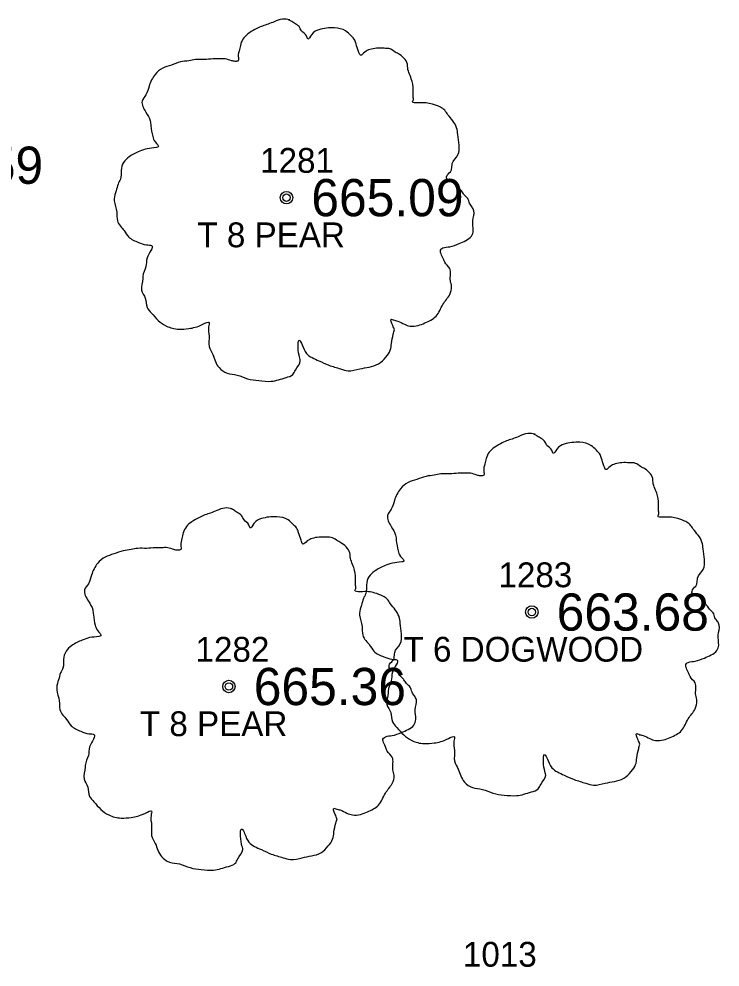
# Model space of a CAD drawing. Extents: x 1655137 to 1657928, y 1003994 to 1005407.
# Drawn here: x 1656195.93 to 1656224.19, y 1004707.02 to 1004745.24 of the extents above; entities that cross this region are included whole.
import ezdxf

# ---------------------------------------------------------------- set-up
doc = ezdxf.new("R2010")
doc.units = 0
for name, color, linetype in [('RD_EX_DV_Prop_txCode', 7, 'Continuous'), ('RD_EX_TX_Driveway_ELEV', 7, 'Continuous'), ('RD_EX_TX_VEG_ELEV', 7, 'Continuous'), ('RD_EX_VEG', 7, 'Continuous'), ('RD_EX_VEG_txCode', 7, 'Continuous'), ('RD_SMD_Locator', 7, 'Continuous')]:
    doc.layers.add(name, color=color, linetype=linetype)

msp = doc.modelspace()

# ---------------------------------------------------------------- linework, layer by layer
at = {"layer": 'RD_EX_VEG'}
for centre, radius in [((1656206.716, 1004738.034), 0.25), ((1656206.703, 1004738.015), 0.0001), ((1656216.604, 1004721.331), 0.25), ((1656216.592, 1004721.312), 0.0001), ((1656204.396, 1004718.329), 0.25), ((1656204.384, 1004718.311), 0.0001)]:
    msp.add_circle(centre, radius, dxfattribs=at)
for points in [[(1656206.848, 1004745.201), (1656206.548, 1004745.226), (1656206.223, 1004745.126), (1656205.973, 1004745.026), (1656205.748, 1004744.951), (1656205.523, 1004744.851), (1656205.223, 1004744.677), (1656204.998, 1004744.477), (1656204.873, 1004744.227), (1656204.823, 1004744.002), (1656204.773, 1004743.727), (1656204.773, 1004743.552), (1656204.649, 1004743.527), (1656204.499, 1004743.552), (1656204.249, 1004743.627), (1656203.999, 1004743.627), (1656203.749, 1004743.627), (1656203.399, 1004743.602), (1656203.049, 1004743.602), (1656202.774, 1004743.552), (1656202.449, 1004743.502), (1656202.075, 1004743.377), (1656201.725, 1004743.252), (1656201.425, 1004743.002), (1656201.175, 1004742.528), (1656201.05, 1004742.178), (1656200.9, 1004741.928), (1656201.05, 1004741.478), (1656201.225, 1004741.128), (1656201.25, 1004740.928), (1656201.325, 1004740.503), (1656201.425, 1004740.279), (1656201.55, 1004740.079), (1656201.475, 1004740.054), (1656201.1, 1004740.004), (1656200.8, 1004739.904), (1656200.375, 1004739.679), (1656200.15, 1004739.454), (1656200.05, 1004739.129), (1656200.026, 1004738.779), (1656199.926, 1004738.579), (1656199.851, 1004738.304), (1656199.826, 1004738.229), (1656199.776, 1004737.905), (1656199.876, 1004737.455), (1656199.901, 1004737.105), (1656200.026, 1004736.88), (1656200.175, 1004736.705), (1656200.35, 1004736.455), (1656200.75, 1004736.23), (1656201.075, 1004736.13), (1656201.275, 1004736.105), (1656201.1, 1004735.606), (1656201.05, 1004735.256), (1656200.925, 1004734.856), (1656200.925, 1004734.781), (1656200.875, 1004734.306), (1656201.025, 1004733.981), (1656201.1, 1004733.606), (1656201.275, 1004733.382), (1656201.55, 1004733.082), (1656201.875, 1004732.857), (1656202.375, 1004732.732), (1656202.774, 1004732.757), (1656203.349, 1004732.932), (1656203.599, 1004733.007), (1656203.574, 1004732.832), (1656203.599, 1004732.457), (1656203.599, 1004732.032), (1656203.749, 1004731.707), (1656203.849, 1004731.432), (1656203.999, 1004731.182), (1656204.324, 1004730.958), (1656204.723, 1004730.883), (1656205.148, 1004730.733), (1656205.598, 1004730.658), (1656206.098, 1004730.633), (1656206.698, 1004730.783), (1656206.972, 1004730.908), (1656207.072, 1004731.083), (1656207.272, 1004731.457), (1656207.222, 1004731.682), (1656207.247, 1004732.282), (1656207.347, 1004732.107), (1656207.522, 1004731.757), (1656208.022, 1004731.457), (1656208.422, 1004731.282), (1656208.897, 1004731.132), (1656209.197, 1004731.058), (1656209.671, 1004731.132), (1656210.046, 1004731.207), (1656210.421, 1004731.332), (1656210.721, 1004731.607), (1656210.896, 1004731.882), (1656210.946, 1004732.157), (1656211.021, 1004732.532), (1656211.071, 1004732.707)], [(1656211.071, 1004732.707), (1656210.996, 1004732.882), (1656210.946, 1004733.132), (1656211.021, 1004733.107), (1656211.196, 1004733.057), (1656211.471, 1004732.932), (1656211.695, 1004732.857), (1656212.02, 1004732.882), (1656212.295, 1004732.982), (1656212.745, 1004733.257), (1656213.02, 1004733.731), (1656213.295, 1004734.131), (1656213.37, 1004734.456), (1656213.32, 1004734.681), (1656213.295, 1004735.181), (1656213.095, 1004735.431), (1656213.045, 1004735.556), (1656212.945, 1004735.955), (1656213.02, 1004736.005), (1656213.295, 1004736.055), (1656213.67, 1004736.18), (1656213.944, 1004736.305), (1656214.169, 1004736.48), (1656214.244, 1004736.705), (1656214.219, 1004737.105), (1656214.269, 1004737.505), (1656214.194, 1004737.655), (1656214.094, 1004737.805), (1656214.019, 1004738.005), (1656213.869, 1004738.154), (1656213.77, 1004738.304), (1656213.67, 1004738.404), (1656213.545, 1004738.554), (1656213.37, 1004738.679), (1656213.22, 1004738.729), (1656213.17, 1004738.879), (1656213.32, 1004739.079), (1656213.37, 1004739.179), (1656213.395, 1004739.404), (1656213.62, 1004739.754), (1656213.67, 1004740.154), (1656213.62, 1004740.578), (1656213.57, 1004740.853), (1656213.42, 1004741.128), (1656213.22, 1004741.378), (1656213.095, 1004741.553), (1656212.92, 1004741.678), (1656212.595, 1004741.803), (1656212.345, 1004741.853), (1656211.995, 1004741.853), (1656211.795, 1004741.903), (1656211.82, 1004741.953), (1656211.82, 1004742.103), (1656211.82, 1004742.378), (1656211.745, 1004742.827), (1656211.595, 1004743.327), (1656211.595, 1004743.352), (1656211.495, 1004743.602), (1656211.271, 1004743.802), (1656211.096, 1004743.902), (1656210.896, 1004744.027), (1656210.646, 1004744.052), (1656210.346, 1004744.052), (1656210.071, 1004744.002), (1656209.871, 1004743.902), (1656209.696, 1004743.777), (1656209.621, 1004743.927), (1656209.521, 1004744.227), (1656209.471, 1004744.377), (1656209.321, 1004744.552), (1656209.097, 1004744.752), (1656208.647, 1004744.876), (1656208.022, 1004744.802), (1656207.722, 1004744.602), (1656207.572, 1004744.427), (1656207.522, 1004744.552), (1656207.322, 1004744.752), (1656207.222, 1004744.926), (1656207.047, 1004745.051), (1656206.898, 1004745.151), (1656206.798, 1004745.201)], [(1656216.736, 1004728.498), (1656216.436, 1004728.523), (1656216.112, 1004728.423), (1656215.862, 1004728.324), (1656215.637, 1004728.249), (1656215.412, 1004728.149), (1656215.112, 1004727.974), (1656214.887, 1004727.774), (1656214.762, 1004727.524), (1656214.712, 1004727.299), (1656214.662, 1004727.024), (1656214.662, 1004726.849), (1656214.537, 1004726.824), (1656214.387, 1004726.849), (1656214.137, 1004726.924), (1656213.887, 1004726.924), (1656213.638, 1004726.924), (1656213.288, 1004726.899), (1656212.938, 1004726.899), (1656212.663, 1004726.849), (1656212.338, 1004726.799), (1656211.963, 1004726.674), (1656211.613, 1004726.549), (1656211.314, 1004726.299), (1656211.064, 1004725.825), (1656210.939, 1004725.475), (1656210.789, 1004725.225), (1656210.939, 1004724.775), (1656211.114, 1004724.425), (1656211.139, 1004724.225), (1656211.214, 1004723.801), (1656211.314, 1004723.576), (1656211.439, 1004723.376), (1656211.364, 1004723.351), (1656210.989, 1004723.301), (1656210.689, 1004723.201), (1656210.264, 1004722.976), (1656210.039, 1004722.751), (1656209.939, 1004722.426), (1656209.914, 1004722.076), (1656209.814, 1004721.876), (1656209.739, 1004721.601), (1656209.714, 1004721.526), (1656209.664, 1004721.202), (1656209.764, 1004720.752), (1656209.789, 1004720.402), (1656209.914, 1004720.177), (1656210.064, 1004720.002), (1656210.239, 1004719.752), (1656210.639, 1004719.527), (1656210.964, 1004719.427), (1656211.164, 1004719.402), (1656210.989, 1004718.903), (1656210.939, 1004718.553), (1656210.814, 1004718.153), (1656210.814, 1004718.078), (1656210.764, 1004717.603), (1656210.914, 1004717.278), (1656210.989, 1004716.904), (1656211.164, 1004716.679), (1656211.439, 1004716.379), (1656211.763, 1004716.154), (1656212.263, 1004716.029), (1656212.663, 1004716.054), (1656213.238, 1004716.229), (1656213.488, 1004716.304), (1656213.463, 1004716.129), (1656213.488, 1004715.754), (1656213.488, 1004715.329), (1656213.638, 1004715.004), (1656213.738, 1004714.729), (1656213.887, 1004714.48), (1656214.212, 1004714.255), (1656214.612, 1004714.18), (1656215.037, 1004714.03), (1656215.487, 1004713.955), (1656215.987, 1004713.93), (1656216.586, 1004714.08), (1656216.861, 1004714.205), (1656216.961, 1004714.38), (1656217.161, 1004714.754), (1656217.111, 1004714.979), (1656217.136, 1004715.579), (1656217.236, 1004715.404), (1656217.411, 1004715.054), (1656217.911, 1004714.754), (1656218.311, 1004714.58), (1656218.785, 1004714.43), (1656219.085, 1004714.355), (1656219.56, 1004714.43), (1656219.935, 1004714.505), (1656220.31, 1004714.63), (1656220.61, 1004714.904), (1656220.784, 1004715.179), (1656220.834, 1004715.454), (1656220.909, 1004715.829), (1656220.959, 1004716.004)], [(1656220.959, 1004716.004), (1656220.884, 1004716.179), (1656220.834, 1004716.429), (1656220.909, 1004716.404), (1656221.084, 1004716.354), (1656221.359, 1004716.229), (1656221.584, 1004716.154), (1656221.909, 1004716.179), (1656222.184, 1004716.279), (1656222.634, 1004716.554), (1656222.909, 1004717.028), (1656223.183, 1004717.428), (1656223.258, 1004717.753), (1656223.208, 1004717.978), (1656223.183, 1004718.478), (1656222.983, 1004718.728), (1656222.933, 1004718.853), (1656222.834, 1004719.252), (1656222.909, 1004719.302), (1656223.183, 1004719.352), (1656223.558, 1004719.477), (1656223.833, 1004719.602), (1656224.058, 1004719.777), (1656224.133, 1004720.002), (1656224.108, 1004720.402), (1656224.158, 1004720.802), (1656224.083, 1004720.952), (1656223.983, 1004721.102), (1656223.908, 1004721.302), (1656223.758, 1004721.451), (1656223.658, 1004721.601), (1656223.558, 1004721.701), (1656223.433, 1004721.851), (1656223.258, 1004721.976), (1656223.108, 1004722.026), (1656223.058, 1004722.176), (1656223.208, 1004722.376), (1656223.258, 1004722.476), (1656223.283, 1004722.701), (1656223.508, 1004723.051), (1656223.558, 1004723.451), (1656223.508, 1004723.875), (1656223.458, 1004724.15), (1656223.308, 1004724.425), (1656223.108, 1004724.675), (1656222.983, 1004724.85), (1656222.809, 1004724.975), (1656222.484, 1004725.1), (1656222.234, 1004725.15), (1656221.884, 1004725.15), (1656221.684, 1004725.2), (1656221.709, 1004725.25), (1656221.709, 1004725.4), (1656221.709, 1004725.675), (1656221.634, 1004726.124), (1656221.484, 1004726.624), (1656221.484, 1004726.649), (1656221.384, 1004726.899), (1656221.159, 1004727.099), (1656220.984, 1004727.199), (1656220.784, 1004727.324), (1656220.535, 1004727.349), (1656220.235, 1004727.349), (1656219.96, 1004727.299), (1656219.76, 1004727.199), (1656219.585, 1004727.074), (1656219.51, 1004727.224), (1656219.41, 1004727.524), (1656219.36, 1004727.674), (1656219.21, 1004727.849), (1656218.985, 1004728.049), (1656218.535, 1004728.174), (1656217.911, 1004728.099), (1656217.611, 1004727.899), (1656217.461, 1004727.724), (1656217.411, 1004727.849), (1656217.211, 1004728.049), (1656217.111, 1004728.224), (1656216.936, 1004728.349), (1656216.786, 1004728.448), (1656216.686, 1004728.498)], [(1656204.528, 1004725.497), (1656204.228, 1004725.522), (1656203.903, 1004725.422), (1656203.654, 1004725.322), (1656203.429, 1004725.247), (1656203.204, 1004725.147), (1656202.904, 1004724.972), (1656202.679, 1004724.772), (1656202.554, 1004724.522), (1656202.504, 1004724.297), (1656202.454, 1004724.022), (1656202.454, 1004723.847), (1656202.329, 1004723.822), (1656202.179, 1004723.847), (1656201.929, 1004723.922), (1656201.679, 1004723.922), (1656201.429, 1004723.922), (1656201.08, 1004723.897), (1656200.73, 1004723.897), (1656200.455, 1004723.847), (1656200.13, 1004723.797), (1656199.755, 1004723.672), (1656199.405, 1004723.547), (1656199.106, 1004723.298), (1656198.856, 1004722.823), (1656198.731, 1004722.473), (1656198.581, 1004722.223), (1656198.731, 1004721.773), (1656198.906, 1004721.423), (1656198.931, 1004721.223), (1656199.006, 1004720.799), (1656199.106, 1004720.574), (1656199.23, 1004720.374), (1656199.156, 1004720.349), (1656198.781, 1004720.299), (1656198.481, 1004720.199), (1656198.056, 1004719.974), (1656197.831, 1004719.749), (1656197.731, 1004719.424), (1656197.706, 1004719.074), (1656197.606, 1004718.875), (1656197.531, 1004718.6), (1656197.506, 1004718.525), (1656197.456, 1004718.2), (1656197.556, 1004717.75), (1656197.581, 1004717.4), (1656197.706, 1004717.175), (1656197.856, 1004717), (1656198.031, 1004716.75), (1656198.431, 1004716.526), (1656198.756, 1004716.426), (1656198.956, 1004716.401), (1656198.781, 1004715.901), (1656198.731, 1004715.551), (1656198.606, 1004715.151), (1656198.606, 1004715.076), (1656198.556, 1004714.601), (1656198.706, 1004714.276), (1656198.781, 1004713.902), (1656198.956, 1004713.677), (1656199.23, 1004713.377), (1656199.555, 1004713.152), (1656200.055, 1004713.027), (1656200.455, 1004713.052), (1656201.03, 1004713.227), (1656201.28, 1004713.302), (1656201.255, 1004713.127), (1656201.28, 1004712.752), (1656201.28, 1004712.327), (1656201.429, 1004712.003), (1656201.529, 1004711.728), (1656201.679, 1004711.478), (1656202.004, 1004711.253), (1656202.404, 1004711.178), (1656202.829, 1004711.028), (1656203.279, 1004710.953), (1656203.778, 1004710.928), (1656204.378, 1004711.078), (1656204.653, 1004711.203), (1656204.753, 1004711.378), (1656204.953, 1004711.753), (1656204.903, 1004711.978), (1656204.928, 1004712.577), (1656205.028, 1004712.402), (1656205.203, 1004712.052), (1656205.703, 1004711.753), (1656206.102, 1004711.578), (1656206.577, 1004711.428), (1656206.877, 1004711.353), (1656207.352, 1004711.428), (1656207.727, 1004711.503), (1656208.102, 1004711.628), (1656208.401, 1004711.903), (1656208.576, 1004712.177), (1656208.626, 1004712.452), (1656208.701, 1004712.827), (1656208.751, 1004713.002)], [(1656208.751, 1004713.002), (1656208.676, 1004713.177), (1656208.626, 1004713.427), (1656208.701, 1004713.402), (1656208.876, 1004713.352), (1656209.151, 1004713.227), (1656209.376, 1004713.152), (1656209.701, 1004713.177), (1656209.976, 1004713.277), (1656210.426, 1004713.552), (1656210.7, 1004714.027), (1656210.975, 1004714.426), (1656211.05, 1004714.751), (1656211, 1004714.976), (1656210.975, 1004715.476), (1656210.775, 1004715.726), (1656210.725, 1004715.851), (1656210.625, 1004716.251), (1656210.7, 1004716.301), (1656210.975, 1004716.351), (1656211.35, 1004716.476), (1656211.625, 1004716.6), (1656211.85, 1004716.775), (1656211.925, 1004717), (1656211.9, 1004717.4), (1656211.95, 1004717.8), (1656211.875, 1004717.95), (1656211.775, 1004718.1), (1656211.7, 1004718.3), (1656211.55, 1004718.45), (1656211.45, 1004718.6), (1656211.35, 1004718.7), (1656211.225, 1004718.85), (1656211.05, 1004718.974), (1656210.9, 1004719.024), (1656210.85, 1004719.174), (1656211, 1004719.374), (1656211.05, 1004719.474), (1656211.075, 1004719.699), (1656211.3, 1004720.049), (1656211.35, 1004720.449), (1656211.3, 1004720.874), (1656211.25, 1004721.149), (1656211.1, 1004721.423), (1656210.9, 1004721.673), (1656210.775, 1004721.848), (1656210.6, 1004721.973), (1656210.276, 1004722.098), (1656210.026, 1004722.148), (1656209.676, 1004722.148), (1656209.476, 1004722.198), (1656209.501, 1004722.248), (1656209.501, 1004722.398), (1656209.501, 1004722.673), (1656209.426, 1004723.123), (1656209.276, 1004723.622), (1656209.276, 1004723.647), (1656209.176, 1004723.897), (1656208.951, 1004724.097), (1656208.776, 1004724.197), (1656208.576, 1004724.322), (1656208.326, 1004724.347), (1656208.027, 1004724.347), (1656207.752, 1004724.297), (1656207.552, 1004724.197), (1656207.377, 1004724.072), (1656207.302, 1004724.222), (1656207.202, 1004724.522), (1656207.152, 1004724.672), (1656207.002, 1004724.847), (1656206.777, 1004725.047), (1656206.327, 1004725.172), (1656205.703, 1004725.097), (1656205.403, 1004724.897), (1656205.253, 1004724.722), (1656205.203, 1004724.847), (1656205.003, 1004725.047), (1656204.903, 1004725.222), (1656204.728, 1004725.347), (1656204.578, 1004725.447), (1656204.478, 1004725.497)]]:
    msp.add_spline(points, degree=3, dxfattribs=at)
at = {"layer": 'RD_SMD_Locator'}
for centre in [(1656206.716, 1004738.034), (1656216.604, 1004721.331), (1656204.396, 1004718.329)]:
    msp.add_circle(centre, 0.15, dxfattribs=at)

# ---------------------------------------------------------------- texts
at = {"layer": 'RD_EX_DV_Prop_txCode'}
msp.add_text('1013', height=1, dxfattribs=at).set_placement((1656213.826, 1004707.036))
at = {"layer": 'RD_EX_TX_Driveway_ELEV'}
msp.add_text('666.59', height=1.5, dxfattribs=at).set_placement((1656190.773, 1004738.591))
at = {"layer": 'RD_EX_TX_VEG_ELEV'}
for s, p in [('665.09', (1656207.716, 1004737.284)), ('663.68', (1656217.604, 1004720.581)), ('665.36', (1656205.396, 1004717.579))]:
    msp.add_text(s, height=1.5, dxfattribs=at).set_placement(p)
at = {"layer": 'RD_EX_VEG_txCode'}
for s, p in [('1281', (1656205.653, 1004739.034)), ('T 8 PEAR', (1656203.125, 1004736.034)), ('1283', (1656215.258, 1004722.331)), ('1282', (1656203.05, 1004719.329)), ('T 6 DOGWOOD', (1656211.431, 1004719.331)), ('T 8 PEAR', (1656200.806, 1004716.329))]:
    msp.add_text(s, height=1, dxfattribs=at).set_placement(p)

doc.saveas('drawing.dxf')
